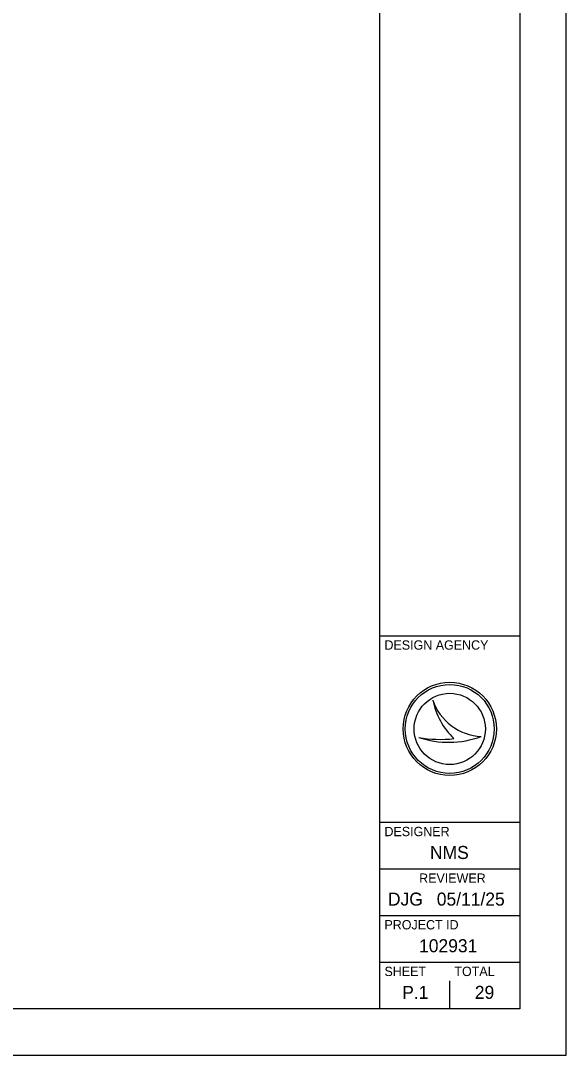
# Model space of a CAD drawing. Extents: x 0 to 34, y 0 to 22.
# Drawn here: x 28.15 to 34, y 0 to 11.1 of the extents above; entities that cross this region are included whole.
import ezdxf

# ---------------------------------------------------------------- set-up
doc = ezdxf.new("R2010")
doc.units = 0
for name, color, linetype in [('SH_Border', 7, 'Continuous'), ('SH_Cut_Line', 7, 'Continuous'), ('SH_Data', 7, 'Continuous')]:
    doc.layers.add(name, color=color, linetype=linetype)

msp = doc.modelspace()

# ---------------------------------------------------------------- linework, layer by layer
at = {"layer": 'SH_Border'}
for p, q in [((32, 0.5), (32, 21.5)), ((32, 4.5), (33.5, 4.5)), ((32, 2.5), (33.5, 2.5)), ((32, 2), (33.5, 2)), ((32, 1.5), (33.5, 1.5)), ((32, 1), (33.5, 1))]:
    msp.add_line(p, q, dxfattribs=at)
msp.add_lwpolyline([(1.5, 21.5), (33.5, 21.5), (33.5, 0.5), (1.5, 0.5)], close=True, dxfattribs=at)
at = {"layer": 'SH_Cut_Line'}
msp.add_lwpolyline([(0, 0), (34, 0), (34, 22), (0, 22)], close=True, dxfattribs=at)
at = {"layer": 'SH_Data'}
for p, q in [((32.567, 3.81), (32.567, 3.81)), ((32.75, 3.5), (32.75, 3.5)), ((32.417, 3.41), (32.417, 3.41)), ((33.087, 3.419), (33.087, 3.419)), ((32.75, 0.5), (32.75, 0.8)), ((32.375, 0.675), (32.375, 0.675))]:
    msp.add_line(p, q, dxfattribs=at)
for radius in [0.5, 0.477, 0.477, 0.382]:
    msp.add_circle((32.75, 3.5), radius, dxfattribs=at)
for centre, radius, start, end in [((33.116, 3.998), 0.58, 198.9257, 198.9319), ((33.347, 3.97), 0.796, 191.6379, 191.6421), ((33.116, 3.998), 0.58, 198.9319, 267.1657), ((33.347, 3.97), 0.796, 191.6421, 226.0947), ((32.739, 4.37), 1.013, 251.4576, 290.0832), ((32.648, 4.654), 1.266, 259.4964, 259.4995), ((32.739, 4.37), 1.013, 251.4527, 251.4576), ((32.648, 4.654), 1.266, 259.4995, 276.6672)]:
    msp.add_arc(centre, radius, start, end, dxfattribs=at)

# ---------------------------------------------------------------- texts
for s, height, p in [('DESIGN AGENCY', 0.1, (32.05, 4.35)), ('DESIGNER', 0.1, (32.05, 2.35)), ('NMS', 0.14, (32.538, 2.105)), ('REVIEWER', 0.1, (32.422, 1.85)), ('DJG', 0.14, (32.087, 1.605)), ('05/11/25', 0.14, (32.611, 1.605)), ('PROJECT ID', 0.1, (32.05, 1.35)), ('102931', 0.14, (32.421, 1.105)), ('SHEET', 0.1, (32.05, 0.85)), ('TOTAL', 0.1, (32.8, 0.85)), ('P.1', 0.14, (32.24, 0.605)), ('29', 0.14, (33.019, 0.605))]:
    msp.add_text(s, height=height, dxfattribs=at).set_placement(p)

doc.saveas('drawing.dxf')
